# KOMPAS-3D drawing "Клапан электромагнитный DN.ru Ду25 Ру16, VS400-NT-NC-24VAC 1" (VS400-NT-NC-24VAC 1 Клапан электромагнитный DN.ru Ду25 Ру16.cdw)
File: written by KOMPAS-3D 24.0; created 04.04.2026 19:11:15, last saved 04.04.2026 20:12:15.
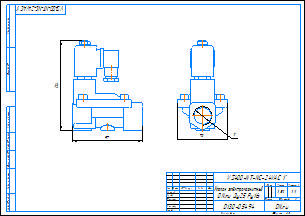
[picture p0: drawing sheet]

Document properties: c3d_UniqueCompID: ef56311e-7521-43dc-8291-0e6108b3d81d; Обозначение: VS400-ET-NC-220VAC 1; Наименование: Клапан электромагнитный DN.ru Ду25 Ру16; Автор: artio; Класс точности: c; Знак неуказанной шероховатости: Шероховатость не задана; Рассекать на разрезах: Да; c3d_UniqueCompID: ef56311e-7521-43dc-8291-0e6108b3d81d; Обозначение: VS400-ET-NC-220VAC 1-2; Наименование: Клапан электромагнитный DN.ru Ду15 Ру16; Автор: artio; Класс точности: c; Знак неуказанной шероховатости: Шероховатость не задана; Рассекать на разрезах: Да; c3d_UniqueCompID: ef56311e-7521-43dc-8291-0e6108b3d81d; Обозначение: VS400-ET-NC-220VAC 3-4; Наименование: Клапан электромагнитный DN.ru Ду20 Ру16; Автор: artio; Класс точности: c; Знак неуказанной шероховатости: Шероховатость не задана; Рассекать на разрезах: Да; c3d_UniqueCompID: ef56311e-7521-43dc-8291-0e6108b3d81d; Обозначение: VS400-ET-NC-220VAC 3-8; Наименование: Клапан электромагнитный DN.ru Ду10 Ру16; Автор: artio; Класс точности: c; Знак неуказанной шероховатости: Шероховатость не задана; Рассекать на разрезах: Да; Автор: artio; Форматы листов документа: A3; Полное имя файла: VS400-NT-NC-24VAC 1 Клапан электромагнитный DN.ru Ду25 Ру16.m3d; Масса: 1.524; Наименование: Клапан электромагнитный DN.ru Ду25 Ру16; Количество листов документа: 1; Примечание: D130-05494

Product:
- Body: Тело 1  | qty 1
    Масса: 1.76797
- Part/product: Клапан электромагнитный DN.ru Ду25 Ру16  | designation VS400-NT-NC-24VAC 1
    Масса: 1.524
    Раздел спецификации: Прочие изделия
    Примечание: D130-05494
    additional columns: ef56311e-7521-43dc-8291-0e6108b3d81d; VS400-ET-NC-220VAC 1; artio; c; Шероховатость не задана; Да

Views: Вид 1, Спереди
Referenced files in C:\Users\artio\OneDrive\Рабочий стол\Клапан электромагнитный DN.ru\VS400-ET-NC\VS400-ET-NC-24VDC\: VS400-ET-NC-24VDC 3-8 Клапан электромагнитный DN.ru Ду10 Ру16.m3d
Referenced files in C:\Users\artio\OneDrive\Рабочий стол\Клапан электромагнитный DN.ru\VS400-NT-NC\VS400-NT-NC-24VAC\: VS400-NT-NC-24VAC 1 Клапан электромагнитный DN.ru Ду25 Ру16.m3d
Referenced files in C:\Users\artio\OneDrive\Рабочий стол\Клапан электромагнитный DN.ru\VS400-ET-NC\: VS400-ET-NC-24VDC 3-8 Клапан электромагнитный DN.ru Ду10 Ру16.cdw
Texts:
  VS400-NT-NC-24VAC 1
  Клапан электромагнитный
  DN.ru Ду25 Ру16
  VS400-NT-NC-24VAC 1"
  VS400-NT-NC-24VAC 1"-
  Клапан электромагнитный DN.ru Ду25 Ру16
  VS400-NT-NC-24VAC 1 Клапан электромагнитный DN.ru Ду25 Ру16
Dimensions and other numbers on the sheet: 0; 3; 2; 4; 70; 1:1; 1; 1,52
